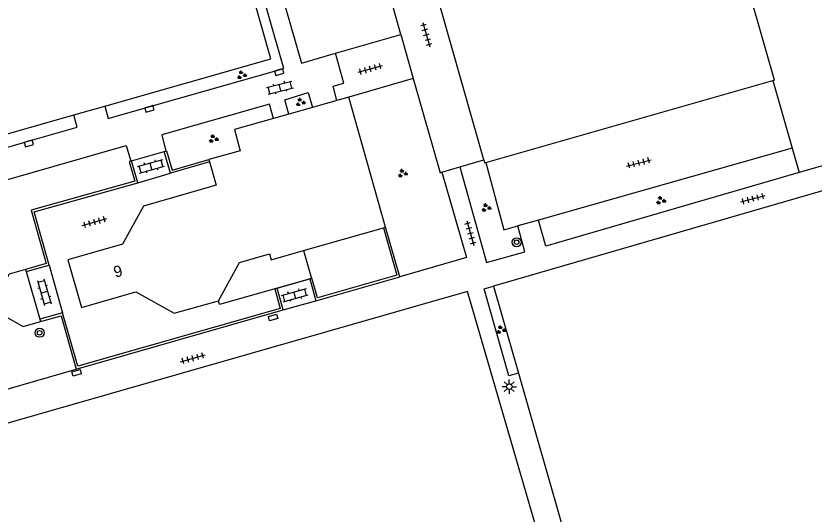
# Model space of a CAD drawing. Extents: x 137999 to 141000, y 397500 to 400501.
# Drawn here: x 138376.2 to 138446.7, y 399191.9 to 399235.9 of the extents above; entities that cross this region are included whole.
import ezdxf

# ---------------------------------------------------------------- set-up
doc = ezdxf.new("R2010")
doc.units = 0
for name, color, linetype in [('gg-afsc-hekwerk', 7, 'Continuous'), ('gg-afsc-muur', 7, 'Continuous'), ('gg-anno-huisnummerreeks BGT', 7, 'Continuous'), ('gg-bbg-hoofdgebouw', 7, 'Continuous'), ('gg-bbg-luifel en loopbrug', 7, 'Continuous'), ('gg-knt-trap', 7, 'Continuous'), ('gg-knt-verharding', 7, 'Continuous'), ('gt-symb-boom', 7, 'Continuous'), ('gt-symb-groenvak', 7, 'Continuous'), ('gt-symb-klinker verharding', 7, 'Continuous'), ('gt-symb-kolk', 7, 'Continuous'), ('gt-symb-kolk center center', 7, 'Continuous'), ('gt-symb-lichtmast', 7, 'Continuous'), ('gt-symb-tegel verharding', 7, 'Continuous')]:
    doc.layers.add(name, color=color, linetype=linetype)

# ---------------------------------------------------------------- blocks, each defined once
blk = doc.blocks.new('gt0-KOLK')
at = {"layer": 'gt-symb-kolk'}
blk.add_lwpolyline([(0, 0), (0.375, 0), (0.375, 0.4), (-0.375, 0.4), (-0.375, 0), (0, 0)], dxfattribs=at)
blk = doc.blocks.new('gt0-KL1')
at = {"layer": 'gt-symb-klinker verharding'}
for p, q in [((-1.15, 0.3), (1.15, 0.3)), ((-1, -0.3), (-1, 0.3)), ((-0.5, 0.3), (-0.5, 0.45)), ((0, -0.3), (0, 0.3)), ((0.5, 0.3), (0.5, 0.45)), ((1, -0.3), (1, 0.3)), ((-1.15, -0.3), (1.15, -0.3)), ((-0.5, -0.45), (-0.5, -0.3)), ((0.5, -0.45), (0.5, -0.3))]:
    blk.add_line(p, q, dxfattribs=at)
blk = doc.blocks.new('gt0-GRVAK')
at = {"layer": 'gt-symb-groenvak'}
for p, q in [((-0.11, 0.189), (-0.228, 0.24)), ((-0.182, 0.153), (0.088, 0.153)), ((-0.091, 0.211), (-0.156, 0.322)), ((-0.047, 0.214), (-0.047, 0.393)), ((-0.004, 0.211), (0.061, 0.322)), ((0.015, 0.189), (0.133, 0.24)), ((0.262, -0.052), (0.197, 0.059)), ((0.305, -0.049), (0.305, 0.13)), ((0.349, -0.052), (0.414, 0.059)), ((-0.245, -0.228), (-0.363, -0.177)), ((-0.318, -0.264), (-0.047, -0.264)), ((-0.226, -0.206), (-0.291, -0.095)), ((-0.183, -0.203), (-0.183, -0.024)), ((-0.139, -0.206), (-0.074, -0.095)), ((-0.12, -0.228), (-0.002, -0.177)), ((0.243, -0.074), (0.125, -0.023)), ((0.17, -0.11), (0.441, -0.11)), ((0.368, -0.074), (0.486, -0.023))]:
    blk.add_line(p, q, dxfattribs=at)
blk = doc.blocks.new('gt0-TEG1')
at = {"layer": 'gt-symb-tegel verharding'}
for p, q in [((-1.125, 0), (1.125, 0)), ((-0.9, -0.25), (-0.9, 0.25)), ((-0.45, -0.25), (-0.45, 0.25)), ((0, -0.25), (0, 0.25)), ((0.45, -0.25), (0.45, 0.25)), ((0.9, -0.25), (0.9, 0.25))]:
    blk.add_line(p, q, dxfattribs=at)
blk = doc.blocks.new('gt0-KOLKCC')
at = {"layer": 'gt-symb-kolk center center'}
blk.add_lwpolyline([(-0.375, 0.2), (0.375, 0.2), (0.375, -0.2), (-0.375, -0.2)], close=True, dxfattribs=at)
blk = doc.blocks.new('gt0-BOOM')
at = {"layer": 'gt-symb-boom'}
for radius in [0.4, 0.2]:
    blk.add_circle((0, 0), radius, dxfattribs=at)
blk = doc.blocks.new('gt0-LMAST')
at = {"layer": 'gt-symb-lichtmast'}
for p, q in [((-0.182, 0.173), (-0.447, 0.438)), ((-0.005, 0.246), (-0.005, 0.621)), ((0.172, 0.173), (0.437, 0.438)), ((-0.255, -0.004), (-0.63, -0.004)), ((-0.182, -0.181), (-0.447, -0.446)), ((-0.005, -0.254), (-0.005, -0.629)), ((0.437, -0.446), (0.172, -0.181)), ((0.245, -0.004), (0.62, -0.004))]:
    blk.add_line(p, q, dxfattribs=at)
blk.add_circle((-0.005, -0.004), 0.25, dxfattribs=at)

msp = doc.modelspace()

# ---------------------------------------------------------------- linework, layer by layer
at = {"layer": 'gg-afsc-hekwerk'}
for p, q in [((138404.41, 399232.648), (138410.189, 399234.32)), ((138410.189, 399234.32), (138411.292, 399230.429)), ((138443.086, 399230.229), (138444.786, 399224.266)), ((138381.287, 399227.195), (138384.025, 399227.974)), ((138466.356, 399225.944), (138418.373, 399212.05)), ((138444.786, 399224.266), (138422.38, 399217.905)), ((138444.786, 399224.266), (138445.403, 399222.101)), ((138415.4, 399222.604), (138417.523, 399223.23)), ((138413.814, 399222.137), (138415.4, 399222.604)), ((138422.38, 399217.905), (138420.531, 399217.38)), ((138418.373, 399212.05), (138420.584, 399204.366)), ((138420.584, 399204.366), (138425.725, 399186.496))]:
    msp.add_line(p, q, dxfattribs=at)
for points in [[(138398.591, 399241.616), (138401.419, 399231.782), (138404.41, 399232.648)], [(138384.025, 399227.974), (138398.69, 399232.146), (138396.359, 399240.37)], [(138363.499, 399231.238), (138365.888, 399222.814), (138381.287, 399227.195)], [(138411.292, 399230.429), (138413.655, 399222.09), (138413.814, 399222.137)], [(138417.702, 399222.989), (138419.307, 399217.032), (138420.531, 399217.38)], [(138426.269, 399176.659), (138416.081, 399211.572), (138365.416, 399197.088), (138375.436, 399162.17)]]:
    msp.add_lwpolyline(points, dxfattribs=at)
at = {"layer": 'gg-afsc-muur'}
for p, q in [((138389.271, 399223.959), (138389.419, 399224.002)), ((138389.833, 399222.039), (138389.271, 399223.959)), ((138386.378, 399223.124), (138386.312, 399223.105)), ((138386.921, 399221.199), (138386.378, 399223.124)), ((138393.277, 399223.047), (138389.833, 399222.039)), ((138410.095, 399212.873), (138408.85, 399217.26)), ((138377.008, 399213.539), (138377.065, 399213.337)), ((138377.065, 399213.337), (138379.096, 399213.91)), ((138402.132, 399212.692), (138402.678, 399210.768)), ((138402.678, 399210.768), (138410.095, 399212.873)), ((138399.792, 399209.948), (138399.243, 399211.871)), ((138381.473, 399204.721), (138399.792, 399209.948)), ((138380.285, 399209.697), (138378.275, 399209.127)), ((138378.275, 399209.127), (138378.332, 399208.925))]:
    msp.add_line(p, q, dxfattribs=at)
for points in [[(138389.419, 399224.002), (138389.473, 399224.018), (138389.976, 399222.3), (138393.22, 399223.25)], [(138386.312, 399223.105), (138386.176, 399223.067), (138386.662, 399221.344), (138377.509, 399218.761), (138378.837, 399214.055), (138377.008, 399213.539)], [(138379.096, 399213.91), (138377.768, 399218.616), (138386.921, 399221.199)], [(138408.648, 399217.203), (138409.836, 399213.018), (138402.823, 399211.027), (138402.334, 399212.749), (138402.132, 399212.692)], [(138399.243, 399211.871), (138399.041, 399211.813), (138399.532, 399210.092), (138381.618, 399204.981), (138380.285, 399209.697)], [(138378.332, 399208.925), (138380.141, 399209.436), (138381.473, 399204.721)]]:
    msp.add_lwpolyline(points, dxfattribs=at)
at = {"layer": 'gg-bbg-hoofdgebouw'}
for p, q in [((138417.702, 399222.989), (138443.086, 399230.229)), ((138443.086, 399230.229), (138443.23, 399230.27)), ((138405.58, 399228.78), (138404.545, 399228.486)), ((138408.85, 399217.26), (138405.58, 399228.78)), ((138404.545, 399228.486), (138402.367, 399227.868)), ((138402.367, 399227.868), (138400.283, 399227.276)), ((138400.283, 399227.276), (138398.938, 399226.895)), ((138393.22, 399223.25), (138393.277, 399223.047)), ((138401.587, 399215.2), (138408.648, 399217.203)), ((138408.648, 399217.203), (138408.85, 399217.26))]:
    msp.add_line(p, q, dxfattribs=at)
for points in [[(138417.523, 399223.23), (138407.06, 399260.03), (138412.91, 399261.68), (138412.35, 399263.63), (138432.11, 399269.28)], [(138443.23, 399230.27), (138440.084, 399241.325), (138441.844, 399241.827), (138436.299, 399261.261), (138434.539, 399260.759), (138432.11, 399269.28)], [(138398.938, 399226.895), (138395.47, 399225.91), (138395.99, 399224.02), (138393.22, 399223.25)], [(138417.523, 399223.23), (138417.6, 399222.96), (138417.702, 399222.989)], [(138393.277, 399223.047), (138393.85, 399221), (138387.43, 399219.12), (138385.59, 399215.77), (138380.74, 399214.38), (138381.95, 399210.17), (138386.77, 399211.56), (138390.15, 399209.67), (138394.06, 399210.76)], [(138394.06, 399210.76), (138395.92, 399214.16), (138398.58, 399214.92), (138398.73, 399214.39), (138401.587, 399215.2)]]:
    msp.add_lwpolyline(points, dxfattribs=at)
at = {"layer": 'gg-bbg-luifel en loopbrug'}
msp.add_lwpolyline([(138401.587, 399215.2), (138402.284, 399212.746), (138394.149, 399210.439), (138394.06, 399210.76)], dxfattribs=at)
at = {"layer": 'gg-knt-trap'}
for p, q in [((138386.378, 399223.124), (138389.271, 399223.959)), ((138386.921, 399221.199), (138389.833, 399222.039)), ((138377.065, 399213.337), (138378.275, 399209.127)), ((138379.096, 399213.91), (138380.285, 399209.697)), ((138399.243, 399211.871), (138402.132, 399212.692)), ((138399.792, 399209.948), (138402.678, 399210.768))]:
    msp.add_line(p, q, dxfattribs=at)
at = {"layer": 'gg-knt-verharding'}
for p, q in [((138411.292, 399230.429), (138405.58, 399228.78)), ((138465.755, 399228.008), (138445.403, 399222.101))]:
    msp.add_line(p, q, dxfattribs=at)
for points in [[(138410.189, 399234.32), (138400.998, 399267.294), (138393.428, 399264.986), (138393.58, 399264.432)], [(138384.025, 399227.974), (138384.323, 399226.868), (138387.901, 399227.917), (138399.831, 399231.301), (138397.182, 399240.58), (138396.359, 399240.37)], [(138404.545, 399228.486), (138404.197, 399229.746), (138405.145, 399230.021), (138404.41, 399232.648)], [(138400.283, 399227.276), (138399.94, 399228.546), (138401.994, 399229.175), (138402.367, 399227.868)], [(138398.938, 399226.895), (138398.576, 399228.145), (138389.042, 399225.423), (138389.419, 399224.002)], [(138365.523, 399221.431), (138377.236, 399224.864), (138381.579, 399226.106), (138381.287, 399227.195)], [(138377.008, 399213.539), (138375.545, 399213.126), (138374.684, 399211.601), (138366.486, 399216.228), (138367.031, 399217.199), (138366.555, 399218.957), (138385.902, 399224.489), (138386.312, 399223.105)], [(138415.4, 399222.604), (138417.775, 399214.14), (138421.143, 399215.078), (138420.531, 399217.38)], [(138413.814, 399222.137), (138415.992, 399214.584), (138410.095, 399212.873)], [(138445.403, 399222.101), (138423.024, 399215.606), (138422.38, 399217.905)], [(138362.272, 399215.332), (138363.863, 399215.778), (138376.792, 399208.49), (138378.332, 399208.925)], [(138420.584, 399204.366), (138419.728, 399204.127), (138417.573, 399211.818), (138418.373, 399212.05)], [(138366.248, 399201.138), (138366.463, 399200.372), (138381.473, 399204.721)]]:
    msp.add_lwpolyline(points, dxfattribs=at)

# ---------------------------------------------------------------- block references
at = {"layer": 'gt-symb-boom'}
for p in [(138420.44, 399215.941), (138378.246, 399207.93)]:
    msp.add_blockref('gt0-BOOM', p, dxfattribs=at)
at = {"layer": 'gt-symb-groenvak'}
for p in [(138396.109, 399230.723), (138401.303, 399228.311), (138393.615, 399225.077), (138410.336, 399222.026), (138433.175, 399219.632), (138417.727, 399218.99), (138419.047, 399208.185)]:
    msp.add_blockref('gt0-GRVAK', p, dxfattribs=at)
at = {"layer": 'gt-symb-klinker verharding'}
for p, rotation in [((138399.514, 399229.615), 14.244742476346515), ((138388.106, 399222.653), 15.189787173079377), ((138378.656, 399211.525), -73.79481463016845), ((138400.815, 399211.26), 15.717252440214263)]:
    msp.add_blockref('gt0-KL1', p, dxfattribs=dict(at, rotation=rotation))
at = {"layer": 'gt-symb-kolk'}
for p, rotation in [((138399.385, 399231.174), -164.10181291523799), ((138387.901, 399227.917), -164.15691788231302), ((138377.236, 399224.864), -164.03098347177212)]:
    msp.add_blockref('gt0-KOLK', p, dxfattribs=dict(at, rotation=rotation))
at = {"layer": 'gt-symb-kolk center center'}
for p, rotation in [((138398.894, 399209.276), 16.496224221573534), ((138381.515, 399204.398), 15.969016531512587)]:
    msp.add_blockref('gt0-KOLKCC', p, dxfattribs=dict(at, rotation=rotation))
at = {"layer": 'gt-symb-lichtmast'}
msp.add_blockref('gt0-LMAST', (138419.787, 399203.171), dxfattribs=at)
at = {"layer": 'gt-symb-tegel verharding'}
for p, rotation in [((138412.448, 399234.3), -74.21205294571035), ((138407.499, 399231.264), 15.425970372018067), ((138431.239, 399222.954), 14.717311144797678), ((138441.335, 399219.786), 14.71731114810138), ((138383.109, 399217.723), 15.551724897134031), ((138416.341, 399216.747), -74.21205294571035), ((138391.801, 399205.676), 15.60693046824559)]:
    msp.add_blockref('gt0-TEG1', p, dxfattribs=dict(at, rotation=rotation))

# ---------------------------------------------------------------- texts
at = {"layer": 'gg-anno-huisnummerreeks BGT'}
msp.add_text('9', height=1, rotation=16, dxfattribs=at).set_placement((138384.953, 399212.795))

doc.saveas('drawing.dxf')
